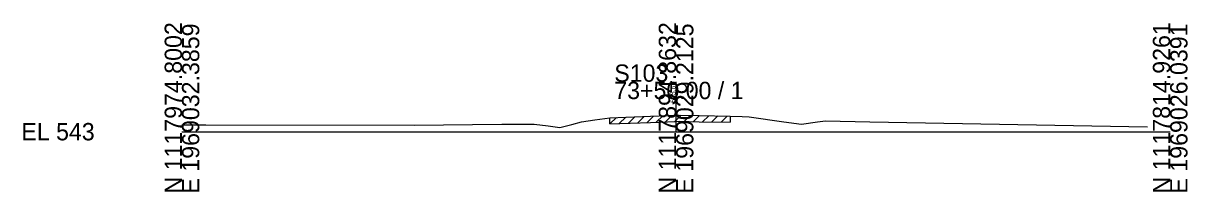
# Model space of a CAD drawing. Extents: x -26 to 163, y -10 to 24018.
# Drawn here: x -25.7 to 162.8, y 21490.3 to 21517.5 of the extents above; entities that cross this region are included whole.
import ezdxf

# ---------------------------------------------------------------- set-up
doc = ezdxf.new("R2010")
doc.units = 0
for name, color, linetype in [('RD_GPK_XS_Cell', 7, 'Continuous'), ('RD_XS_ExGround', 7, 'Continuous'), ('RD_XS_ExPaveRet', 7, 'Continuous'), ('RD_XS_TX_Elev_EX', 7, 'Continuous')]:
    doc.layers.add(name, color=color, linetype=linetype)

msp = doc.modelspace()

# ---------------------------------------------------------------- linework, layer by layer
at = {"layer": 'RD_GPK_XS_Cell'}
for p, q in [((80, 21500), (80, 21508.06)), ((0, 21500), (80, 21500)), ((80, 21500), (160, 21500))]:
    msp.add_line(p, q, dxfattribs=at)
at = {"layer": 'RD_XS_ExGround'}
msp.add_lwpolyline([(0, 21501.12), (3.84, 21501.13), (37.61, 21501.07), (51.79, 21501.2), (57, 21501.21), (59.27, 21500.93), (61.17, 21500.65), (63.13, 21501.14), (64.68, 21501.57), (66.82, 21501.89), (69.3, 21502.25), (75.84, 21502.5), (80, 21502.67), (80.5, 21502.69), (83.72, 21502.61), (88.78, 21502.52), (90.68, 21502.46), (91.83, 21502.42), (97.47, 21501.61), (100.33, 21501.2), (102.91, 21501.58), (104.22, 21501.74), (111.39, 21501.61), (156.35, 21500.78)], dxfattribs=at)
at = {"layer": 'RD_XS_ExPaveRet'}
for p, q in [((69.3, 21501.25), (70.34, 21502.29)), ((69.3, 21501.25), (69.3, 21502.25)), ((70.8, 21501.31), (71.84, 21502.35)), ((72.3, 21501.37), (73.34, 21502.41)), ((73.8, 21501.42), (74.84, 21502.46)), ((75.3, 21501.48), (76.34, 21502.52)), ((76.8, 21501.54), (77.84, 21502.58)), ((78.3, 21501.6), (79.34, 21502.64)), ((79.8, 21501.66), (80.82, 21502.68)), ((81.3, 21501.67), (82.28, 21502.64)), ((82.8, 21501.63), (83.78, 21502.61)), ((84.3, 21501.6), (85.28, 21502.58)), ((85.8, 21501.57), (86.78, 21502.56)), ((87.3, 21501.55), (88.28, 21502.53)), ((88.78, 21502.52), (88.78, 21501.52)), ((69.3, 21501.25), (75.84, 21501.5)), ((75.84, 21501.5), (80, 21501.67)), ((80, 21501.67), (80.5, 21501.69)), ((80.5, 21501.69), (83.72, 21501.61)), ((83.72, 21501.61), (88.78, 21501.52))]:
    msp.add_line(p, q, dxfattribs=at)

# ---------------------------------------------------------------- texts
at = {"layer": 'RD_GPK_XS_Cell'}
for s, p in [('N 1117974.8002', (0, 21490)), ('E 1969032.3859', (2.8, 21490)), ('N 1117894.8632', (80, 21490)), ('E 1969029.2125', (82.8, 21490)), ('N 1117814.9261', (160, 21490)), ('E 1969026.0391', (162.8, 21490))]:
    msp.add_text(s, height=2.8, rotation=90, dxfattribs=at).set_placement(p)
for s, p in [('S103', (70, 21508.06)), ('73+50.00 / 1', (70, 21505.26)), ('EL 543', (-26, 21498.6))]:
    msp.add_text(s, height=2.8, dxfattribs=at).set_placement(p)
at = {"layer": 'RD_XS_TX_Elev_EX'}
msp.add_text('545.67', height=0.8, rotation=90, dxfattribs=at).set_placement((79.9, 21504.67))

doc.saveas('drawing.dxf')
